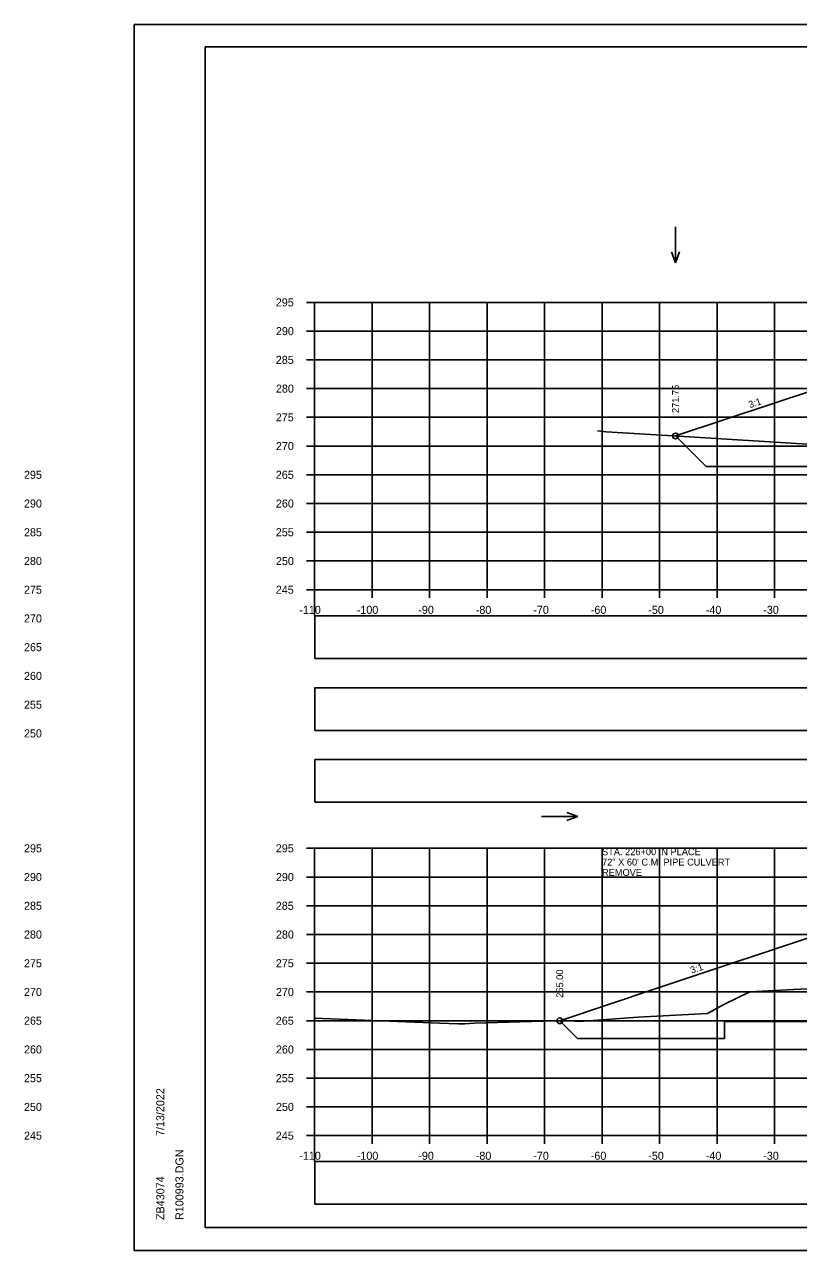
# Model space of a CAD drawing. Extents: x 4667 to 1632277, y -2100 to 724501.
# Drawn here: x 5616.7 to 5751.3, y -43.7 to 169.6 of the extents above; entities that cross this region are included whole.
import ezdxf

# ---------------------------------------------------------------- set-up
doc = ezdxf.new("R2010")
doc.units = 0
for name, color, linetype in [('R_Axis', 7, 'Continuous'), ('R_Axis Annot', 7, 'Continuous'), ('R_Border', 7, 'Continuous'), ('R_Exist Surface', 7, 'Continuous'), ('R_Fin Surface', 7, 'Continuous'), ('R_Fin Surface Annot', 7, 'Continuous'), ('R_Grid', 7, 'Continuous'), ('R_No Plot', 7, 'Continuous'), ('R_Proposed CofA', 7, 'Continuous'), ('R_ROW', 7, 'Continuous'), ('R_Water Annot', 7, 'Continuous')]:
    doc.layers.add(name, color=color, linetype=linetype)

msp = doc.modelspace()

# ---------------------------------------------------------------- linework, layer by layer
at = {"layer": 'R_Axis'}
for p, q in [((5665.78, 121.26), (5667.18, 121.26)), ((5667.18, 71.26), (5667.18, 121.26)), ((5665.78, 116.26), (5667.18, 116.26)), ((5665.78, 111.26), (5667.18, 111.26)), ((5665.78, 106.26), (5667.18, 106.26)), ((5665.78, 101.26), (5667.18, 101.26)), ((5665.78, 96.26), (5667.18, 96.26)), ((5665.78, 91.26), (5667.18, 91.26)), ((5665.78, 86.26), (5667.18, 86.26)), ((5665.78, 81.26), (5667.18, 81.26)), ((5665.78, 76.26), (5667.18, 76.26)), ((5665.78, 71.26), (5667.18, 71.26)), ((5667.18, 71.26), (5947.18, 71.26)), ((5667.18, 69.86), (5667.18, 71.26)), ((5677.18, 69.86), (5677.18, 71.26)), ((5687.18, 69.86), (5687.18, 71.26)), ((5697.18, 69.86), (5697.18, 71.26)), ((5707.18, 69.86), (5707.18, 71.26)), ((5717.18, 69.86), (5717.18, 71.26)), ((5727.18, 69.86), (5727.18, 71.26)), ((5737.18, 69.86), (5737.18, 71.26)), ((5747.18, 69.86), (5747.18, 71.26)), ((5665.78, 26.26), (5667.18, 26.26)), ((5667.18, -23.74), (5667.18, 26.26)), ((5665.78, 21.26), (5667.18, 21.26)), ((5665.78, 16.26), (5667.18, 16.26)), ((5665.78, 11.26), (5667.18, 11.26)), ((5665.78, 6.26), (5667.18, 6.26)), ((5665.78, 1.26), (5667.18, 1.26)), ((5665.78, -3.74), (5667.18, -3.74)), ((5665.78, -8.74), (5667.18, -8.74)), ((5665.78, -13.74), (5667.18, -13.74)), ((5665.78, -18.74), (5667.18, -18.74)), ((5665.78, -23.74), (5667.18, -23.74)), ((5667.18, -23.74), (5947.18, -23.74)), ((5667.18, -25.14), (5667.18, -23.74)), ((5677.18, -25.14), (5677.18, -23.74)), ((5687.18, -25.14), (5687.18, -23.74)), ((5697.18, -25.14), (5697.18, -23.74)), ((5707.18, -25.14), (5707.18, -23.74)), ((5717.18, -25.14), (5717.18, -23.74)), ((5727.18, -25.14), (5727.18, -23.74)), ((5737.18, -25.14), (5737.18, -23.74)), ((5747.18, -25.14), (5747.18, -23.74))]:
    msp.add_line(p, q, dxfattribs=at)
at = {"layer": 'R_Border'}
for p, q in [((5648.18, 165.72), (5964.36, 165.72)), ((5648.18, -39.74), (5648.18, 165.72)), ((5648.18, -39.74), (5648.18, -39.74)), ((5964.36, -39.74), (5648.18, -39.74))]:
    msp.add_line(p, q, dxfattribs=at)
at = {"layer": 'R_Exist Surface'}
for points in [[(5716.38, 98.89), (5717.91, 98.72), (5731.49, 97.92), (5752.87, 96.58)], [(5667.18, -3.27), (5688.89, -4.17), (5692.2, -4.28), (5693.24, -4.28), (5695.01, -4.16), (5710.96, -3.71), (5713.29, -3.85), (5723.4, -3.13), (5735.51, -2.48), (5738.35, -0.92), (5742.87, 1.27), (5750.5, 1.69), (5754.32, 1.84)]]:
    msp.add_lwpolyline(points, dxfattribs=at)
at = {"layer": 'R_Fin Surface'}
for points in [[(5729.97, 98.01), (5754.83, 106.3), (5757.68, 107.25), (5759.68, 107.33), (5767.18, 107.63), (5777.18, 107.83), (5787.18, 107.63), (5791.18, 107.47), (5795.55, 106.38), (5796.75, 106.08), (5817.02, 99.32), (5851.63, 98.63)], [(5709.82, -3.74), (5726.62, 1.87), (5757.62, 12.19), (5757.7, 12.21), (5763.18, 13.58), (5767.18, 13.79), (5777.18, 14.32), (5787.18, 14.84), (5794.68, 15.24), (5796.68, 15.34), (5802.34, 13.46), (5815.75, 8.99), (5827.46, 5.08), (5843.2, -0.16), (5844.93, -0.74), (5863.64, 5.5)]]:
    msp.add_lwpolyline(points, dxfattribs=at)
at = {"layer": 'R_Grid'}
for p, q in [((5667.18, 121.26), (5947.18, 121.26)), ((5667.18, 71.26), (5667.18, 121.26)), ((5677.18, 71.26), (5677.18, 121.26)), ((5687.18, 71.26), (5687.18, 121.26)), ((5697.18, 71.26), (5697.18, 121.26)), ((5707.18, 71.26), (5707.18, 121.26)), ((5717.18, 71.26), (5717.18, 121.26)), ((5727.18, 71.26), (5727.18, 121.26)), ((5737.18, 71.26), (5737.18, 121.26)), ((5747.18, 71.26), (5747.18, 121.26)), ((5667.18, 116.26), (5947.18, 116.26)), ((5667.18, 111.26), (5947.18, 111.26)), ((5667.18, 106.26), (5947.18, 106.26)), ((5667.18, 101.26), (5947.18, 101.26)), ((5667.18, 96.26), (5947.18, 96.26)), ((5667.18, 91.26), (5947.18, 91.26)), ((5667.18, 86.26), (5947.18, 86.26)), ((5667.18, 81.26), (5947.18, 81.26)), ((5667.18, 76.26), (5947.18, 76.26)), ((5667.18, 71.26), (5947.18, 71.26)), ((5667.18, 26.26), (5947.18, 26.26)), ((5667.18, -23.74), (5667.18, 26.26)), ((5677.18, -23.74), (5677.18, 26.26)), ((5687.18, -23.74), (5687.18, 26.26)), ((5697.18, -23.74), (5697.18, 26.26)), ((5707.18, -23.74), (5707.18, 26.26)), ((5717.18, -23.74), (5717.18, 26.26)), ((5727.18, -23.74), (5727.18, 26.26)), ((5737.18, -23.74), (5737.18, 26.26)), ((5747.18, -23.74), (5747.18, 26.26)), ((5667.18, 21.26), (5947.18, 21.26)), ((5667.18, 16.26), (5947.18, 16.26)), ((5667.18, 11.26), (5947.18, 11.26)), ((5667.18, 6.26), (5947.18, 6.26)), ((5667.18, 1.26), (5947.18, 1.26)), ((5667.18, -3.74), (5947.18, -3.74)), ((5667.18, -8.74), (5947.18, -8.74)), ((5667.18, -13.74), (5947.18, -13.74)), ((5667.18, -18.74), (5947.18, -18.74)), ((5667.18, -23.74), (5947.18, -23.74))]:
    msp.add_line(p, q, dxfattribs=at)
at = {"layer": 'R_No Plot'}
for p, q in [((5635.78, 169.61), (5969.12, 169.61)), ((5667.18, 69.86), (5667.18, 66.79)), ((5667.18, -25.14), (5667.18, -28.21)), ((5635.78, -43.72), (5969.12, -43.72))]:
    msp.add_line(p, q, dxfattribs=at)
for points in [[(5635.78, 169.61), (5969.12, 169.61), (5969.12, -43.72), (5635.78, -43.72)], [(5882.1, 165.72), (5901.72, 165.72), (5901.72, 155.84), (5917.84, 155.84), (5941.04, 155.84), (5941.04, 131.51), (5964.36, 131.51), (5964.36, -39.74), (5648.18, -39.74), (5648.18, 165.72)]]:
    msp.add_lwpolyline(points, close=True, dxfattribs=at)
for centre in [(5729.97, 98.01), (5709.82, -3.74)]:
    msp.add_circle(centre, 0.5, dxfattribs=at)
at = {"layer": 'R_Proposed CofA'}
for points in [[(5667.23, 59.32), (5947.13, 59.32), (5947.13, 66.74), (5667.23, 66.74)], [(5667.23, 46.79), (5947.13, 46.79), (5947.13, 54.21), (5667.23, 54.21)], [(5667.23, 34.27), (5947.13, 34.27), (5947.13, 41.69), (5667.23, 41.69)], [(5667.23, -35.68), (5947.13, -35.68), (5947.13, -28.26), (5667.23, -28.26)]]:
    msp.add_lwpolyline(points, close=True, dxfattribs=at)
at = {"layer": 'R_ROW'}
for p, q in [((5729.97, 98.01), (5735.29, 92.7)), ((5735.29, 92.7), (5807.21, 92.7)), ((5709.82, -3.74), (5712.92, -6.85)), ((5738.5, -6.85), (5738.5, -3.85)), ((5738.5, -3.85), (5764.97, -3.85)), ((5738.5, -6.85), (5712.92, -6.85))]:
    msp.add_line(p, q, dxfattribs=at)
at = {"layer": 'R_Water Annot'}
for p, q in [((5729.97, 134.4), (5729.97, 128.12)), ((5729.97, 128.12), (5729.27, 130.04)), ((5729.97, 128.12), (5730.67, 130.04)), ((5712.96, 31.79), (5711.03, 32.49)), ((5706.67, 31.79), (5712.96, 31.79)), ((5712.96, 31.79), (5711.03, 31.09))]:
    msp.add_line(p, q, dxfattribs=at)

# ---------------------------------------------------------------- texts
at = {"layer": 'R_Axis Annot'}
for s, p in [('295', (5660.44, 120.56)), ('290', (5660.46, 115.56)), ('285', (5660.44, 110.56)), ('280', (5660.46, 105.56)), ('275', (5660.44, 100.56)), ('270', (5660.46, 95.56)), ('295', (5616.64, 90.56)), ('265', (5660.44, 90.56)), ('290', (5616.64, 85.56)), ('260', (5660.46, 85.56)), ('285', (5616.64, 80.56)), ('255', (5660.44, 80.56)), ('280', (5616.64, 75.56)), ('250', (5660.46, 75.56)), ('275', (5616.64, 70.56)), ('245', (5660.44, 70.56)), ('-110', (5664.52, 67.06)), ('-100', (5674.52, 67.06)), ('-90', (5685.22, 67.06)), ('-80', (5695.22, 67.06)), ('-70', (5705.22, 67.06)), ('-60', (5715.22, 67.06)), ('-50', (5725.22, 67.06)), ('-40', (5735.22, 67.06)), ('-30', (5745.22, 67.06)), ('270', (5616.64, 65.56)), ('265', (5616.64, 60.56)), ('260', (5616.64, 55.56)), ('255', (5616.64, 50.56)), ('250', (5616.64, 45.56)), ('295', (5616.64, 25.56)), ('295', (5660.44, 25.56)), ('290', (5616.64, 20.56)), ('290', (5660.46, 20.56)), ('285', (5616.64, 15.56)), ('285', (5660.44, 15.56)), ('280', (5616.64, 10.56)), ('280', (5660.46, 10.56)), ('275', (5616.64, 5.56)), ('275', (5660.44, 5.56)), ('270', (5616.64, 0.56)), ('270', (5660.46, 0.56)), ('265', (5616.64, -4.44)), ('265', (5660.44, -4.44)), ('260', (5616.64, -9.44)), ('260', (5660.46, -9.44)), ('255', (5616.64, -14.44)), ('255', (5660.44, -14.44)), ('250', (5616.64, -19.44)), ('250', (5660.46, -19.44)), ('245', (5616.64, -24.44)), ('245', (5660.44, -24.44)), ('-110', (5664.52, -27.94)), ('-100', (5674.52, -27.94)), ('-90', (5685.22, -27.94)), ('-80', (5695.22, -27.94)), ('-70', (5705.22, -27.94)), ('-60', (5715.22, -27.94)), ('-50', (5725.22, -27.94)), ('-40', (5735.22, -27.94)), ('-30', (5745.22, -27.94))]:
    msp.add_text(s, height=1.4, dxfattribs=at).set_placement(p)
at = {"layer": 'R_Border'}
for s, p in [('7/13/2022', (5641.05, -23.81)), ('R100993.DGN', (5644.38, -38.42)), ('ZB43074', (5641.05, -38.42))]:
    msp.add_text(s, height=1.4, rotation=90, dxfattribs=at).set_placement(p)
at = {"layer": 'R_Fin Surface Annot'}
for s, rotation, p in [('271.75', 90, (5730.57, 102.01)), ('3:1', 18.4349, (5742.88, 102.84)), ('265.00', 90, (5710.42, 0.26)), ('3:1', 18.4349, (5732.77, 4.44))]:
    msp.add_text(s, height=1.2, rotation=rotation, dxfattribs=at).set_placement(p)
at = {"layer": 'R_Water Annot'}
for s, p in [('STA. 226+00 IN PLACE', (5717.18, 25.06)), ('72" X 60\' C.M. PIPE CULVERT', (5717.18, 23.26)), ('REMOVE', (5717.18, 21.46))]:
    msp.add_text(s, height=1.2, dxfattribs=at).set_placement(p)

doc.saveas('drawing.dxf')
